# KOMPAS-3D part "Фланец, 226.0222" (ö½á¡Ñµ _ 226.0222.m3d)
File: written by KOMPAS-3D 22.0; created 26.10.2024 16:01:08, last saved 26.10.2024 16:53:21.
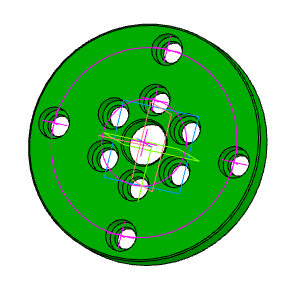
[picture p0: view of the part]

Document properties: Автор: aleksander.larionov.10@gmail.com; Полное имя файла: C:\Мои папки\Работа\Крышки, фланцы\226.0222\Фланец _ 226.0222.m3d

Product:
- Part/product: Фланец  | designation 226.0222
    Материал: Сталь 45 ГОСТ 1050-2013 (density 7810 kg/m3)
    Масса: 2.039272

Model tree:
1. Эскиз:1
2. Элемент выдавливания:1
     Расстояние 1 = 18
3. Эскиз:2  (with: Элемент выдавливания:1)
4. Отверстие:1  (with: Элемент выдавливания:1)
     Глубина выреза = 18; Диаметр отверстия = 14; Угол конуса дна = 118; Расстояние 1 = 27.5; Диаметр цековки = 20; Глубина цековки = 11
5. Массив по точкам:1
6. Экземпляр ( 1 )  (with: Отверстие:1, Эскиз:2)
7. Экземпляр ( 2 )  (with: Отверстие:1, Эскиз:2)
8. Экземпляр ( 3 )  (with: Отверстие:1, Эскиз:2)
9. Экземпляр ( 4 )  (with: Отверстие:1, Эскиз:2)
10. Массив по концентрической сетке:1  (with: Отверстие:1, Эскиз:2)  (6 pattern instances)
     Шаг 2 = 360
11. Отверстие:2  (with: Элемент выдавливания:1)
     Глубина выреза = 18; Диаметр отверстия = 28; Угол конуса дна = 118
12. Фаска:1  (with: Отверстие:2, Элемент выдавливания:1)  (labels: Сталь 45 ГОСТ 1050-2013)
     Угол = 45; Длина 1 = 1; Длина 2 = 1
